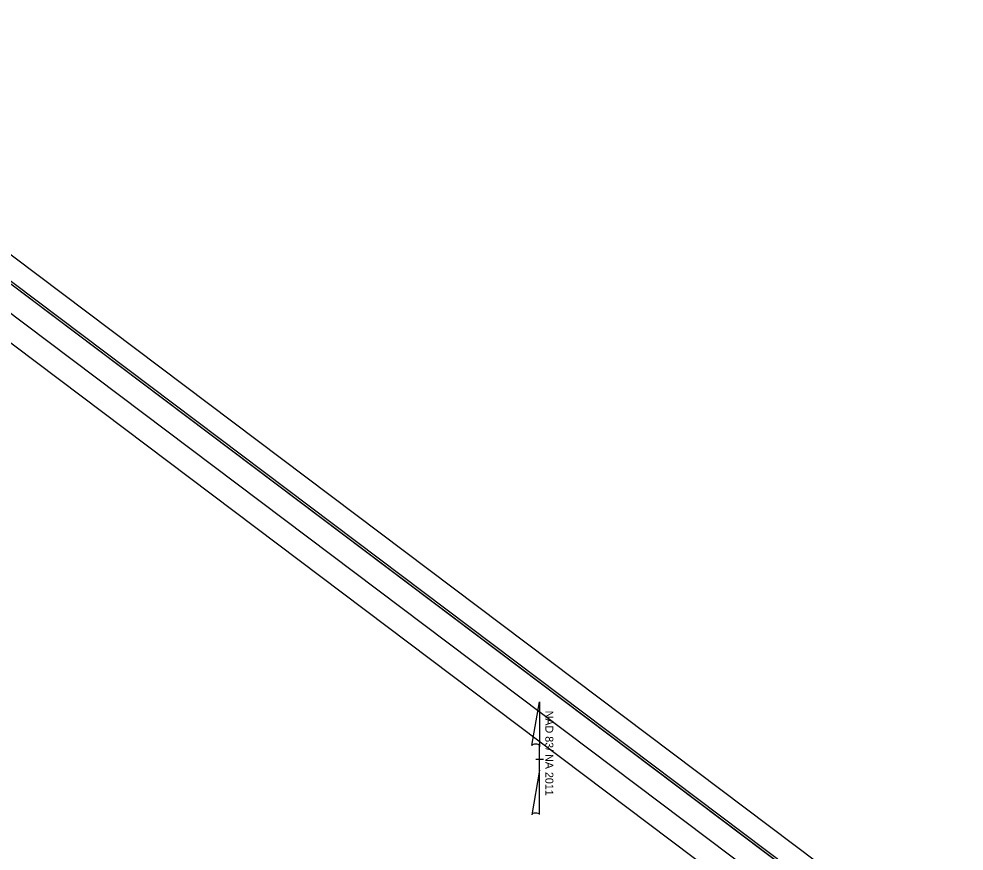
# Model space of a CAD drawing. Extents: x 2296955 to 2298159, y 600182 to 601317.
# Drawn here: x 2297557 to 2298159, y 600787 to 601317 of the extents above; entities that cross this region are included whole.
import ezdxf

# ---------------------------------------------------------------- set-up
doc = ezdxf.new("R2010")
doc.units = 0
for name, color, linetype in [('Exist DTM Drainline Cogo Comment', 7, 'Continuous'), ('Exist DTM Drainline Cogo Elevation', 7, 'Continuous'), ('Exist Property Iron Pin CELL', 7, 'Continuous'), ('Exist Property Iron Pin Cogo Number', 7, 'Continuous'), ('Exist Roads Curbs Cogo Number', 7, 'Continuous'), ('Exist Roads Curbs Cogo Point CELL', 7, 'Continuous'), ('Exist Roads EOP Cogo Comment', 7, 'Continuous')]:
    doc.layers.add(name, color=color, linetype=linetype)

msp = doc.modelspace()

# ---------------------------------------------------------------- linework, layer by layer
at = {"layer": 'Exist DTM Drainline Cogo Comment'}
msp.add_lwpolyline([(2298148.7, 600700.2), (2297350.15, 601301.97), (2296969.16, 600796.39), (2297767.7, 600194.63)], close=True, dxfattribs=at)
at = {"layer": 'Exist DTM Drainline Cogo Elevation'}
msp.add_lwpolyline([(2298141.78, 600703.5), (2297423.02, 601245.14), (2297043.87, 600742.01), (2297762.63, 600200.36)], close=True, dxfattribs=at)
at = {"layer": 'Exist Property Iron Pin CELL'}
for p, q in [((2297883.62, 600854.36), (2297888.54, 600882.17)), ((2297888.57, 600882.17), (2297888.57, 600853.49)), ((2297888.57, 600838.61), (2297888.57, 600854.33)), ((2297888.57, 600853.49), (2297888.57, 600854.3)), ((2297886.2, 600845.57), (2297891, 600845.57)), ((2297888.57, 600838.61), (2297883.56, 600810.26)), ((2297888.6, 600810.38), (2297888.57, 600838.61))]:
    msp.add_line(p, q, dxfattribs=at)
for centre, start_param, end_param in [((2297886.1, 600854.07), 0.216388, 2.908219), ((2297886.1, 600810.16), 0.201328, 3.141593)]:
    msp.add_ellipse(centre, major_axis=(2.54, -0.02), ratio=0.461098, start_param=start_param, end_param=end_param, dxfattribs=at)
at = {"layer": 'Exist Property Iron Pin Cogo Number'}
msp.add_lwpolyline([(2297342.87, 601088.91), (2297238.27, 600783.77), (2297197.22, 600664.01), (2297465.89, 600461.56), (2297631.65, 600336.65), (2298039.33, 600622.14), (2298039.33, 600622.14), (2297969.72, 600674.6), (2298027.87, 600751.78), (2297428.93, 601203.11)], close=True, dxfattribs=at)
at = {"layer": 'Exist Roads Curbs Cogo Number'}
msp.add_lwpolyline([(2297423.02, 601245.14), (2297043.89, 600742.01), (2297762.65, 600200.36), (2298069.63, 600607.76), (2297973.78, 600679.99), (2298045.93, 600775.73)], close=True, dxfattribs=at)
at = {"layer": 'Exist Roads Curbs Cogo Point CELL'}
msp.add_lwpolyline([(2298158.96, 600709.34), (2297352.03, 601317.42), (2296954.82, 600790.33), (2297761.75, 600182.24)], close=True, dxfattribs=at)
at = {"layer": 'Exist Roads EOP Cogo Comment'}
msp.add_lwpolyline([(2297425.97, 601224.13), (2297064.9, 600744.96), (2297759.7, 600221.37), (2298062.62, 600623.38), (2297966.76, 600695.61), (2298024.92, 600772.78)], close=True, dxfattribs=at)

# ---------------------------------------------------------------- texts
at = {"layer": 'Exist Property Iron Pin CELL'}
msp.add_text('NAD 83/ NA 2011', height=5.1, rotation=270.02394, dxfattribs=at).set_placement((2297892.2, 600876.58))

doc.saveas('drawing.dxf')
